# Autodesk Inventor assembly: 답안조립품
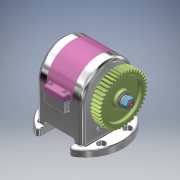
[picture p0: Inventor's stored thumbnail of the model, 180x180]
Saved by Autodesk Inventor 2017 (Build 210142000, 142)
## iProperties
Part Number: 답안조립품
Material: 일반
Document SubType Name: Assembly
Designer: MRC
Author: MRC
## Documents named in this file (21)
- C:\Users\MRC\Desktop\740804V1006\답안조립품.iam
- C:\Users\MRC\Desktop\740804V1006\본체.ipt
- C:\Users\MRC\Desktop\740804V1006\오일레스 부시 20 15.ipt
- C:\Users\MRC\Desktop\740804V1006\부시 커버.ipt
- C:\Users\MRC\Desktop\740804V1006\육각 소켓 머리 볼트 M4x10.ipt
- C:\Users\MRC\Desktop\740804V1006\링크.ipt
- C:\Users\MRC\Desktop\740804V1006\펀치.ipt
- C:\Users\MRC\Desktop\740804V1006\핀.ipt
- C:\Users\MRC\Desktop\740804V1006\E형 멈춤링 10-8.ipt
- C:\Users\MRC\Desktop\740804V1006\깊은 홈 볼 베어링 6904.ipt
- C:\Users\MRC\Desktop\740804V1006\칼라.ipt
- C:\Users\MRC\Desktop\740804V1006\편심축.ipt
- C:\Users\MRC\Desktop\740804V1006\뒷커버.ipt
- C:\Users\MRC\Desktop\740804V1006\오일실 20 32 5.ipt
- C:\Users\MRC\Desktop\740804V1006\앞커버.ipt
- C:\Users\MRC\Desktop\740804V1006\평행키 5x5x12.ipt
- C:\Users\MRC\Desktop\740804V1006\스퍼 기어.ipt
- C:\Users\MRC\Desktop\740804V1006\평와셔 M10.ipt
- C:\Users\MRC\Desktop\740804V1006\스프링 와셔 M10.ipt
- C:\Users\MRC\Desktop\740804V1006\육각 너트 M10x1.ipt
- C:\Users\MRC\Desktop\740804V1006\윗커버.ipt
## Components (2 placed, 2 different names)
1. 핀:1
2. E형 멈춤링 10-8:1 — 각도:2
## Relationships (1: Angle 1)
- 각도:2 [Angle]: E형 멈춤링 10-8:1
